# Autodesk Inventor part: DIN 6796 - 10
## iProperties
Created: 2006-02
Part Number: DIN 6796 - 10
Material: Steel, Mild
Description: Conical Spring Washer
Document SubType Name: Modeling
Standard: DIN 6796
Designer: Phil Trethewie
Standards Organization: DIN
Language: en-US
Size Designation: 10
Categories: <MemberInstance><Categories><Category DisplayName="Fasteners" InternalName="e4da775c-781d-43d5-af7c-5136215cf5a6" Mnemonic="FSTN"><Category DisplayName="Washers
IsCustomPart: 1
Author: Phil Trethewie
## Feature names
1. Body [Extrusion]
